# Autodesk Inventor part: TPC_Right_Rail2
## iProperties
Shininess: 64.0
Length Units: 11272
Angle Units: 11279
Time Units: 11290
Mass Units: 11286
Length Display Precision: 3
Angle Display Precision: 2
Compacted: True
Part Number: TPC_Right_Rail2
Document SubType Name: Modeling
Created: 2004-08
Designer: Lori
Manufacturer: Standard
Standards Organization: Custom
Material: Steel, Mild
Density: 0.0
Volumn: 0.0
Area: 0.0
PropertySet Name: Model Information
Control State: 0
Master: False
Checked Out: False
Author: Lori
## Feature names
1. Base1
